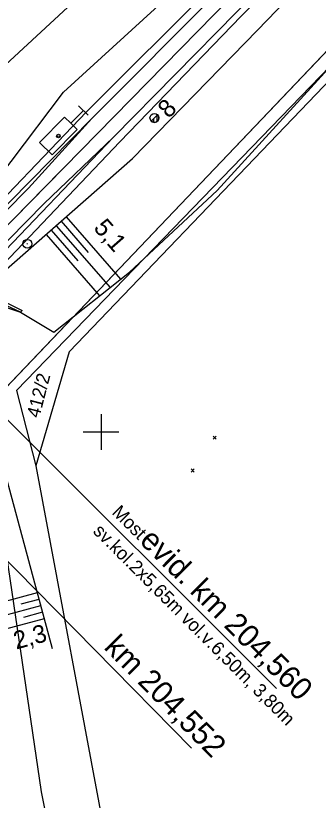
# Model space of a CAD drawing. Extents: x -800194 to -799078, y -1007177 to -1006597.
# Drawn here: x -799409.6 to -799375.6, y -1006941.3 to -1006853.3 of the extents above; entities that cross this region are included whole.
import ezdxf

# ---------------------------------------------------------------- set-up
doc = ezdxf.new("R2010")
doc.units = 0
for name, color, linetype in [('_návrh', 7, 'Continuous'), ('Ramove udaje', 7, 'Continuous'), ('Vrstva 1', 7, 'Continuous'), ('Vrstva 11', 7, 'Continuous'), ('Vrstva 18', 7, 'Continuous'), ('Vrstva 4', 7, 'Continuous'), ('Vrstva 48', 7, 'Continuous'), ('Vrstva 49', 7, 'Continuous'), ('Vrstva 5', 7, 'Continuous'), ('Vrstva 53', 7, 'Continuous'), ('Vrstva 55', 7, 'Continuous'), ('Vrstva 57', 7, 'Continuous'), ('Vrstva 7', 7, 'Continuous')]:
    doc.layers.add(name, color=color, linetype=linetype)

msp = doc.modelspace()

# ---------------------------------------------------------------- linework, layer by layer
at = {"layer": '_návrh'}
msp.add_line((-799415.714, -1006882.127), (-799404.558, -1006870.75), dxfattribs=at)
at = {"layer": 'Ramove udaje'}
for p, q in [((-799400, -1006898), (-799400, -1006902)), ((-799402, -1006900), (-799400, -1006900)), ((-799400, -1006900), (-799398, -1006900))]:
    msp.add_line(p, q, dxfattribs=at)
at = {"layer": 'Vrstva 1'}
msp.add_line((-799415.714, -1006882.127), (-799297.339, -1006761.401), dxfattribs=at)
at = {"layer": 'Vrstva 11'}
for p, q in [((-799393.651, -1006864.414), (-799394.357, -1006865.13)), ((-799394.068, -1006865.267), (-799394.071, -1006864.84)), ((-799393.693, -1006865.166), (-799393.699, -1006864.463))]:
    msp.add_line(p, q, dxfattribs=at)
msp.add_circle((-799394.004, -1006864.772), 0.503, dxfattribs=at)
msp.add_arc((-799394.004, -1006864.772), 0.503, 225.43085, 45.43085, dxfattribs=at)
at = {"layer": 'Vrstva 18'}
msp.add_line((-799380.318, -1006928.766), (-799419.546, -1006889.62), dxfattribs=at)
for points in [[(-799414.182, -1006884.2), (-799414.808, -1006884.66), (-799409.032, -1006886.579), (-799414.182, -1006884.2)], [(-799413.881, -1006883.908), (-799408.874, -1006886.377), (-799409.032, -1006886.579)]]:
    msp.add_lwpolyline(points, dxfattribs=at)
at = {"layer": 'Vrstva 4'}
for points in [[(-799415.349, -1006878.386), (-799401.641, -1006864.104), (-799387.486, -1006849.959), (-799372.535, -1006834.618), (-799359.471, -1006821.017), (-799348.425, -1006810.321), (-799332.246, -1006792.656), (-799316.193, -1006777.023)], [(-799414.896, -1006878.87), (-799401.02, -1006864.85), (-799386.827, -1006850.567), (-799372.152, -1006835.069), (-799358.827, -1006821.464), (-799347.624, -1006811), (-799330.977, -1006793.164), (-799315.559, -1006777.544)], [(-799412.388, -1006881.287), (-799398.609, -1006866.93), (-799384.751, -1006852.862), (-799369.474, -1006837.434), (-799356.035, -1006824.081), (-799345.419, -1006813.083), (-799328.801, -1006795.774), (-799312.796, -1006779.76)], [(-799411.693, -1006881.939), (-799397.907, -1006867.466), (-799384.258, -1006853.369), (-799368.884, -1006838.066), (-799355.624, -1006824.532), (-799352.562, -1006821.889), (-799351.649, -1006821.039), (-799351.009, -1006819.785)], [(-799510.394, -1006958.536), (-799498.027, -1006951.328), (-799477.988, -1006937.435), (-799460.33, -1006923.117), (-799451.862, -1006915.581), (-799443.604, -1006907.9), (-799435.444, -1006900.067), (-799428.64, -1006893.299), (-799422.817, -1006887.511), (-799415.998, -1006880.595), (-799408.158, -1006872.652), (-799401.02, -1006864.85)], [(-799509.248, -1006960.724), (-799497.456, -1006953.809), (-799476.495, -1006939.437), (-799458.707, -1006924.982), (-799450.277, -1006917.43), (-799441.932, -1006909.717), (-799433.783, -1006901.867), (-799426.9, -1006895.092), (-799421.037, -1006889.182), (-799414.218, -1006882.281), (-799406.443, -1006874.417), (-799398.609, -1006866.93)]]:
    msp.add_lwpolyline(points, dxfattribs=at)
at = {"layer": 'Vrstva 48'}
for p, q in [((-799403.924, -1006875.875), (-799397.802, -1006882.869)), ((-799405.053, -1006876.863), (-799398.98, -1006883.8)), ((-799404.488, -1006876.369), (-799401.44, -1006879.852)), ((-799406.181, -1006877.851), (-799400.158, -1006884.732)), ((-799405.617, -1006877.357), (-799402.593, -1006880.811)), ((-799407.172, -1006918.053), (-799411.191, -1006919.139)), ((-799406.976, -1006918.777), (-799409.024, -1006919.33)), ((-799406.781, -1006919.501), (-799410.952, -1006920.628)), ((-799406.585, -1006920.225), (-799408.709, -1006920.799)), ((-799406.389, -1006920.949), (-799410.713, -1006922.118))]:
    msp.add_line(p, q, dxfattribs=at)
at = {"layer": 'Vrstva 49'}
for p, q in [((-799387.424, -1006900.452), (-799387.07, -1006900.806)), ((-799387.424, -1006900.806), (-799387.07, -1006900.452)), ((-799389.887, -1006904.151), (-799389.533, -1006904.505)), ((-799389.887, -1006904.505), (-799389.533, -1006904.151))]:
    msp.add_line(p, q, dxfattribs=at)
for points in [[(-799327.095, -1006776.084), (-799339.676, -1006790.63), (-799358.716, -1006807.195), (-799375.729, -1006824.95), (-799393.254, -1006842.64), (-799410.738, -1006858.834), (-799418.516, -1006867.679), (-799420.397, -1006870.813)], [(-799416.02, -1006877.454), (-799404.211, -1006861.901), (-799389.752, -1006848.65), (-799373.943, -1006833.474), (-799360.851, -1006819.663), (-799350.223, -1006808.887), (-799332.885, -1006792.133), (-799317.349, -1006776.174)], [(-799411.244, -1006882.282), (-799396.463, -1006869.344), (-799382.442, -1006854.946), (-799367.277, -1006839.246), (-799355.518, -1006825.988), (-799351.844, -1006822.661), (-799350.97, -1006821.769), (-799343.258, -1006815.248), (-799325.688, -1006798.253), (-799311.274, -1006781.732)], [(-799405.305, -1006888.801), (-799396.789, -1006882.068), (-799386.952, -1006872.928), (-799372.538, -1006857.15), (-799356.348, -1006840.041), (-799339.512, -1006822.205), (-799317.886, -1006801.135), (-799302.503, -1006781.465)], [(-799426.038, -1006858.234), (-799426.419, -1006863.568), (-799427.212, -1006869.673), (-799426.968, -1006870.003), (-799426.4, -1006870.552), (-799426.115, -1006870.824), (-799426.018, -1006877.519), (-799424.103, -1006883.903), (-799422.705, -1006885.358), (-799423.751, -1006886.402), (-799420.096, -1006889.979), (-799419.086, -1006888.964), (-799412.022, -1006900.113), (-799405.487, -1006924.286)], [(-799413.881, -1006883.908), (-799408.874, -1006886.377), (-799409.032, -1006886.579), (-799405.305, -1006888.801)]]:
    msp.add_lwpolyline(points, dxfattribs=at)
at = {"layer": 'Vrstva 5'}
msp.add_line((-799389.844, -1006935.446), (-799426.915, -1006897.844), dxfattribs=at)
at = {"layer": 'Vrstva 53'}
msp.add_lwpolyline([(-799312.398, -1006791.976), (-799331.37, -1006811.87), (-799413.75, -1006898.23), (-799418.41, -1006902.53), (-799423.07, -1006906.83), (-799433.4, -1006916.39), (-799469.5, -1006946.86), (-799487.22, -1006958.47), (-799495.25, -1006963.74), (-799521.98, -1006977.8), (-799546.71, -1006987.83)], dxfattribs=at)
at = {"layer": 'Vrstva 55'}
msp.add_line((-799413.75, -1006898.23), (-799331.37, -1006811.87), dxfattribs=at)
for points in [[(-799329.14, -1006812.3), (-799409.48, -1006895.36), (-799407.32, -1006903.81)], [(-799328.26, -1006812.47), (-799403.59, -1006891), (-799407.32, -1006903.81)], [(-799413.75, -1006898.23), (-799411.99, -1006904.75), (-799406.72, -1006940.36), (-799397.01, -1006988.73)], [(-799407.32, -1006903.81), (-799399.52, -1006945.6), (-799393.3, -1006959.22)]]:
    msp.add_lwpolyline(points, dxfattribs=at)
at = {"layer": 'Vrstva 7'}
for p, q in [((-799401.449, -1006864.476), (-799402.519, -1006863.424)), ((-799404.985, -1006866.805), (-799404.588, -1006866.802)), ((-799408.32, -1006878.93), (-799408.25, -1006878.858))]:
    msp.add_line(p, q, dxfattribs=at)
msp.add_lwpolyline([(-799401.984, -1006863.95), (-799403.386, -1006865.377), (-799404.099, -1006864.676), (-799406.902, -1006867.529), (-799405.475, -1006868.931), (-799402.672, -1006866.078), (-799403.386, -1006865.377)], dxfattribs=at)
for centre, radius in [((-799404.787, -1006866.803), 0.2), ((-799408.285, -1006878.894), 0.5)]:
    msp.add_circle(centre, radius, dxfattribs=at)

# ---------------------------------------------------------------- texts
at = {"layer": 'Vrstva 11'}
msp.add_text('8', height=2, rotation=45.43085, dxfattribs=at).set_placement((-799392.413, -1006864.91))
at = {"layer": 'Vrstva 18'}
for s, height, p in [('Most', 1.5, (-799398.873, -1006909.11)), ('sv.kol.2x5,65m vol.v.6,50m, 3,80m', 1.5, (-799400.992, -1006911.233)), ('evid. km 204,560', 2.5, (-799395.797, -1006912.325))]:
    msp.add_text(s, height=height, rotation=315.05951, dxfattribs=at).set_placement(p)
at = {"layer": 'Vrstva 48'}
for s, rotation, p in [('5,1', 311.19608, (-799400.935, -1006877.17)), ('2,3', 15.12789, (-799409.526, -1006924.407))]:
    msp.add_text(s, height=2, rotation=rotation, dxfattribs=at).set_placement(p)
at = {"layer": 'Vrstva 5'}
msp.add_text('km 204,552', height=2.5, rotation=314.59271, dxfattribs=at).set_placement((-799399.785, -1006924.248))
at = {"layer": 'Vrstva 57'}
msp.add_text('412/2', height=1.5, rotation=75.43615, dxfattribs=at).set_placement((-799406.937, -1006898.504))

doc.saveas('drawing.dxf')
